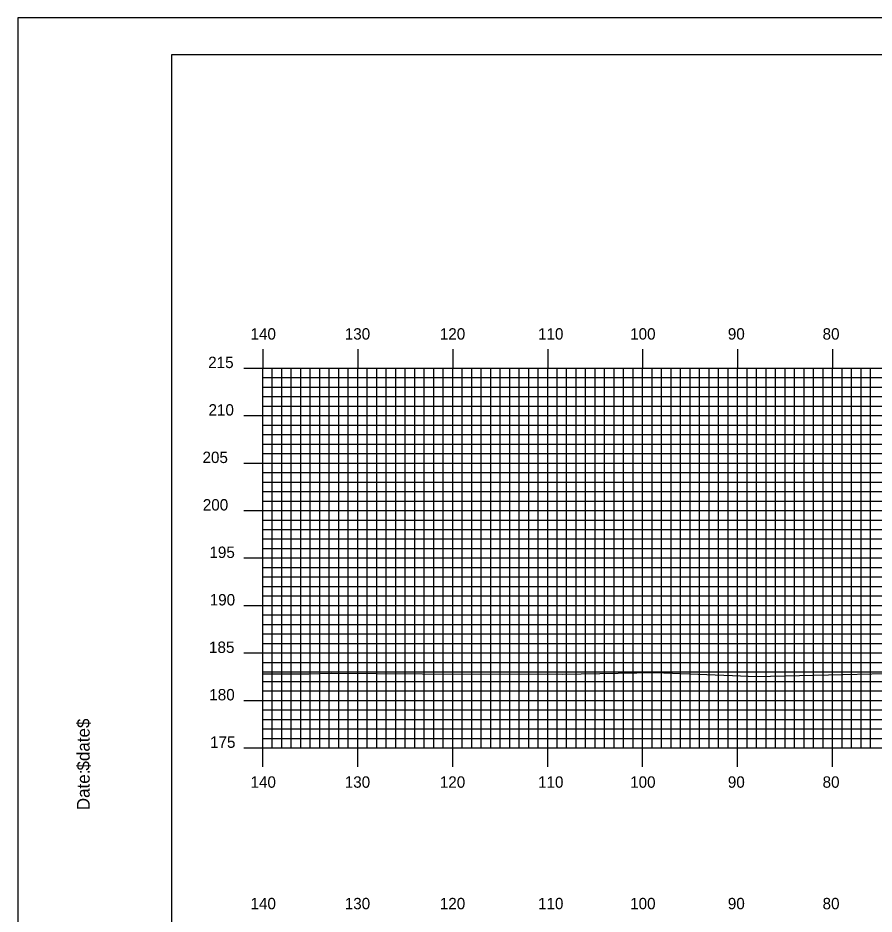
# Model space of a CAD drawing. Extents: x 1809800 to 1810143, y 442591 to 442811.
# Drawn here: x 1809799.6 to 1809889.7, y 442716.2 to 442810.5 of the extents above; entities that cross this region are included whole.
import ezdxf

# ---------------------------------------------------------------- set-up
doc = ezdxf.new("R2010")
doc.units = 0
for name, color, linetype in [('BORDER', 7, 'Continuous'), ('H_V ANNOTATION', 7, 'Continuous'), ('MAJOR', 7, 'Continuous'), ('MINOR', 7, 'Continuous'), ('PLOT BOUNDARY', 7, 'Continuous'), ('S_Roadway_Centerline', 7, 'Continuous')]:
    doc.layers.add(name, color=color, linetype=linetype)

msp = doc.modelspace()

# ---------------------------------------------------------------- linework, layer by layer
at = {"layer": 'BORDER'}
msp.add_lwpolyline([(1809815.75, 442596.665), (1810135.75, 442596.665), (1810135.75, 442806.665), (1809815.75, 442806.665)], close=True, dxfattribs=at)
at = {"layer": 'MAJOR'}
for p, q in [((1809825.35, 442775.669), (1809825.35, 442773.665)), ((1809835.35, 442775.669), (1809835.35, 442773.665)), ((1809845.35, 442775.669), (1809845.35, 442773.665)), ((1809855.35, 442775.669), (1809855.35, 442773.665)), ((1809865.35, 442775.669), (1809865.35, 442773.665)), ((1809875.35, 442775.669), (1809875.35, 442773.665)), ((1809885.35, 442775.669), (1809885.35, 442773.665)), ((1809823.346, 442773.665), (1809825.35, 442773.665)), ((1809825.35, 442773.665), (1810105.35, 442773.665)), ((1809825.35, 442733.665), (1809825.35, 442773.665)), ((1809825.35, 442733.665), (1809825.35, 442773.665)), ((1809825.35, 442773.665), (1810105.35, 442773.665)), ((1809835.35, 442733.665), (1809835.35, 442773.665)), ((1809845.35, 442733.665), (1809845.35, 442773.665)), ((1809855.35, 442733.665), (1809855.35, 442773.665)), ((1809865.35, 442733.665), (1809865.35, 442773.665)), ((1809875.35, 442733.665), (1809875.35, 442773.665)), ((1809885.35, 442733.665), (1809885.35, 442773.665)), ((1809823.346, 442768.665), (1809825.35, 442768.665)), ((1809825.35, 442768.665), (1810105.35, 442768.665)), ((1809823.346, 442763.665), (1809825.35, 442763.665)), ((1809825.35, 442763.665), (1810105.35, 442763.665)), ((1809823.346, 442758.665), (1809825.35, 442758.665)), ((1809825.35, 442758.665), (1810105.35, 442758.665)), ((1809823.346, 442753.665), (1809825.35, 442753.665)), ((1809825.35, 442753.665), (1810105.35, 442753.665)), ((1809823.346, 442748.665), (1809825.35, 442748.665)), ((1809825.35, 442748.665), (1810105.35, 442748.665)), ((1809823.346, 442743.665), (1809825.35, 442743.665)), ((1809825.35, 442743.665), (1810105.35, 442743.665)), ((1809823.346, 442738.665), (1809825.35, 442738.665)), ((1809825.35, 442738.665), (1810105.35, 442738.665)), ((1809823.346, 442733.665), (1809825.35, 442733.665)), ((1809825.35, 442733.665), (1810105.35, 442733.665)), ((1809825.35, 442733.665), (1810105.35, 442733.665)), ((1809825.35, 442731.661), (1809825.35, 442733.665)), ((1809835.35, 442731.661), (1809835.35, 442733.665)), ((1809845.35, 442731.661), (1809845.35, 442733.665)), ((1809855.35, 442731.661), (1809855.35, 442733.665)), ((1809865.35, 442731.661), (1809865.35, 442733.665)), ((1809875.35, 442731.661), (1809875.35, 442733.665)), ((1809885.35, 442731.661), (1809885.35, 442733.665))]:
    msp.add_line(p, q, dxfattribs=at)
at = {"layer": 'MINOR'}
for p, q in [((1809826.35, 442733.665), (1809826.35, 442773.665)), ((1809827.35, 442733.665), (1809827.35, 442773.665)), ((1809828.35, 442733.665), (1809828.35, 442773.665)), ((1809829.35, 442733.665), (1809829.35, 442773.665)), ((1809830.35, 442733.665), (1809830.35, 442773.665)), ((1809831.35, 442733.665), (1809831.35, 442773.665)), ((1809832.35, 442733.665), (1809832.35, 442773.665)), ((1809833.35, 442733.665), (1809833.35, 442773.665)), ((1809834.35, 442733.665), (1809834.35, 442773.665)), ((1809836.35, 442733.665), (1809836.35, 442773.665)), ((1809837.35, 442733.665), (1809837.35, 442773.665)), ((1809838.35, 442733.665), (1809838.35, 442773.665)), ((1809839.35, 442733.665), (1809839.35, 442773.665)), ((1809840.35, 442733.665), (1809840.35, 442773.665)), ((1809841.35, 442733.665), (1809841.35, 442773.665)), ((1809842.35, 442733.665), (1809842.35, 442773.665)), ((1809843.35, 442733.665), (1809843.35, 442773.665)), ((1809844.35, 442733.665), (1809844.35, 442773.665)), ((1809846.35, 442733.665), (1809846.35, 442773.665)), ((1809847.35, 442733.665), (1809847.35, 442773.665)), ((1809848.35, 442733.665), (1809848.35, 442773.665)), ((1809849.35, 442733.665), (1809849.35, 442773.665)), ((1809850.35, 442733.665), (1809850.35, 442773.665)), ((1809851.35, 442733.665), (1809851.35, 442773.665)), ((1809852.35, 442733.665), (1809852.35, 442773.665)), ((1809853.35, 442733.665), (1809853.35, 442773.665)), ((1809854.35, 442733.665), (1809854.35, 442773.665)), ((1809856.35, 442733.665), (1809856.35, 442773.665)), ((1809857.35, 442733.665), (1809857.35, 442773.665)), ((1809858.35, 442733.665), (1809858.35, 442773.665)), ((1809859.35, 442733.665), (1809859.35, 442773.665)), ((1809860.35, 442733.665), (1809860.35, 442773.665)), ((1809861.35, 442733.665), (1809861.35, 442773.665)), ((1809862.35, 442733.665), (1809862.35, 442773.665)), ((1809863.35, 442733.665), (1809863.35, 442773.665)), ((1809864.35, 442733.665), (1809864.35, 442773.665)), ((1809866.35, 442733.665), (1809866.35, 442773.665)), ((1809867.35, 442733.665), (1809867.35, 442773.665)), ((1809868.35, 442733.665), (1809868.35, 442773.665)), ((1809869.35, 442733.665), (1809869.35, 442773.665)), ((1809870.35, 442733.665), (1809870.35, 442773.665)), ((1809871.35, 442733.665), (1809871.35, 442773.665)), ((1809872.35, 442733.665), (1809872.35, 442773.665)), ((1809873.35, 442733.665), (1809873.35, 442773.665)), ((1809874.35, 442733.665), (1809874.35, 442773.665)), ((1809876.35, 442733.665), (1809876.35, 442773.665)), ((1809877.35, 442733.665), (1809877.35, 442773.665)), ((1809878.35, 442733.665), (1809878.35, 442773.665)), ((1809879.35, 442733.665), (1809879.35, 442773.665)), ((1809880.35, 442733.665), (1809880.35, 442773.665)), ((1809881.35, 442733.665), (1809881.35, 442773.665)), ((1809882.35, 442733.665), (1809882.35, 442773.665)), ((1809883.35, 442733.665), (1809883.35, 442773.665)), ((1809884.35, 442733.665), (1809884.35, 442773.665)), ((1809886.35, 442733.665), (1809886.35, 442773.665)), ((1809887.35, 442733.665), (1809887.35, 442773.665)), ((1809888.35, 442733.665), (1809888.35, 442773.665)), ((1809889.35, 442733.665), (1809889.35, 442773.665)), ((1809825.35, 442772.665), (1810105.35, 442772.665)), ((1809825.35, 442772.665), (1809827.354, 442772.665)), ((1809825.35, 442771.665), (1810105.35, 442771.665)), ((1809825.35, 442771.665), (1809827.354, 442771.665)), ((1809825.35, 442770.665), (1810105.35, 442770.665)), ((1809825.35, 442770.665), (1809827.354, 442770.665)), ((1809825.35, 442769.665), (1810105.35, 442769.665)), ((1809825.35, 442769.665), (1809827.354, 442769.665)), ((1809825.35, 442767.665), (1810105.35, 442767.665)), ((1809825.35, 442767.665), (1809827.354, 442767.665)), ((1809825.35, 442766.665), (1810105.35, 442766.665)), ((1809825.35, 442766.665), (1809827.354, 442766.665)), ((1809825.35, 442765.665), (1810105.35, 442765.665)), ((1809825.35, 442765.665), (1809827.354, 442765.665)), ((1809825.35, 442764.665), (1810105.35, 442764.665)), ((1809825.35, 442764.665), (1809827.354, 442764.665)), ((1809825.35, 442762.665), (1810105.35, 442762.665)), ((1809825.35, 442762.665), (1809827.354, 442762.665)), ((1809825.35, 442761.665), (1810105.35, 442761.665)), ((1809825.35, 442761.665), (1809827.354, 442761.665)), ((1809825.35, 442760.665), (1810105.35, 442760.665)), ((1809825.35, 442760.665), (1809827.354, 442760.665)), ((1809825.35, 442759.665), (1810105.35, 442759.665)), ((1809825.35, 442759.665), (1809827.354, 442759.665)), ((1809825.35, 442757.665), (1810105.35, 442757.665)), ((1809825.35, 442757.665), (1809827.354, 442757.665)), ((1809825.35, 442756.665), (1810105.35, 442756.665)), ((1809825.35, 442756.665), (1809827.354, 442756.665)), ((1809825.35, 442755.665), (1810105.35, 442755.665)), ((1809825.35, 442755.665), (1809827.354, 442755.665)), ((1809825.35, 442754.665), (1810105.35, 442754.665)), ((1809825.35, 442754.665), (1809827.354, 442754.665)), ((1809825.35, 442752.665), (1810105.35, 442752.665)), ((1809825.35, 442752.665), (1809827.354, 442752.665)), ((1809825.35, 442751.665), (1810105.35, 442751.665)), ((1809825.35, 442751.665), (1809827.354, 442751.665)), ((1809825.35, 442750.665), (1810105.35, 442750.665)), ((1809825.35, 442750.665), (1809827.354, 442750.665)), ((1809825.35, 442749.665), (1810105.35, 442749.665)), ((1809825.35, 442749.665), (1809827.354, 442749.665)), ((1809825.35, 442747.665), (1810105.35, 442747.665)), ((1809825.35, 442747.665), (1809827.354, 442747.665)), ((1809825.35, 442746.665), (1810105.35, 442746.665)), ((1809825.35, 442746.665), (1809827.354, 442746.665)), ((1809825.35, 442745.665), (1810105.35, 442745.665)), ((1809825.35, 442745.665), (1809827.354, 442745.665)), ((1809825.35, 442744.665), (1810105.35, 442744.665)), ((1809825.35, 442744.665), (1809827.354, 442744.665)), ((1809825.35, 442742.665), (1810105.35, 442742.665)), ((1809825.35, 442742.665), (1809827.354, 442742.665)), ((1809825.35, 442741.665), (1810105.35, 442741.665)), ((1809825.35, 442741.665), (1809827.354, 442741.665)), ((1809825.35, 442740.665), (1810105.35, 442740.665)), ((1809825.35, 442740.665), (1809827.354, 442740.665)), ((1809825.35, 442739.665), (1810105.35, 442739.665)), ((1809825.35, 442739.665), (1809827.354, 442739.665)), ((1809825.35, 442737.665), (1810105.35, 442737.665)), ((1809825.35, 442737.665), (1809827.354, 442737.665)), ((1809825.35, 442736.665), (1810105.35, 442736.665)), ((1809825.35, 442736.665), (1809827.354, 442736.665)), ((1809825.35, 442735.665), (1810105.35, 442735.665)), ((1809825.35, 442735.665), (1809827.354, 442735.665)), ((1809825.35, 442734.665), (1810105.35, 442734.665)), ((1809825.35, 442734.665), (1809827.354, 442734.665))]:
    msp.add_line(p, q, dxfattribs=at)
at = {"layer": 'PLOT BOUNDARY'}
msp.add_lwpolyline([(1809799.564, 442590.547), (1810139.564, 442590.547), (1810139.564, 442810.547), (1809799.564, 442810.547)], close=True, dxfattribs=at)
at = {"layer": 'S_Roadway_Centerline'}
msp.add_lwpolyline([(1809825.35, 442741.451), (1809830.203, 442741.479), (1809832.611, 442741.529), (1809842.155, 442741.48), (1809856.934, 442741.444), (1809866.66, 442741.604), (1809874.804, 442741.278), (1809877.292, 442741.187), (1809898.611, 442741.656)], dxfattribs=at)

# ---------------------------------------------------------------- texts
at = {"layer": 'BORDER'}
for s, p in [('$date$', (1809807.12, 442731.275)), ('Date:', (1809807.12, 442727.099))]:
    msp.add_text(s, height=1.3392, rotation=90, dxfattribs=at).set_placement(p)
at = {"layer": 'H_V ANNOTATION'}
for s, p in [('140', (1809824.055, 442776.665)), ('130', (1809833.98, 442776.665)), ('120', (1809843.991, 442776.665)), ('110', (1809854.334, 442776.665)), ('100', (1809864.034, 442776.665)), ('90', (1809874.323, 442776.665)), ('80', (1809884.301, 442776.665)), ('215', (1809819.599, 442773.665)), ('210', (1809819.631, 442768.665)), ('205', (1809819, 442763.665)), ('200', (1809819.032, 442758.665)), ('195', (1809819.728, 442753.665)), ('190', (1809819.76, 442748.665)), ('185', (1809819.685, 442743.665)), ('180', (1809819.717, 442738.665)), ('175', (1809819.792, 442733.665)), ('140', (1809824.055, 442729.465)), ('130', (1809833.98, 442729.465)), ('120', (1809843.991, 442729.465)), ('110', (1809854.334, 442729.465)), ('100', (1809864.034, 442729.465)), ('90', (1809874.323, 442729.465)), ('80', (1809884.301, 442729.465)), ('140', (1809824.055, 442716.665)), ('130', (1809833.98, 442716.665)), ('120', (1809843.991, 442716.665)), ('110', (1809854.334, 442716.665)), ('100', (1809864.034, 442716.665)), ('90', (1809874.323, 442716.665)), ('80', (1809884.301, 442716.665))]:
    msp.add_text(s, height=1.2, dxfattribs=at).set_placement(p)
at = {"layer": 'MAJOR'}
msp.add_text('-', height=0.012, dxfattribs=at).set_placement((1809825.341, 442733.665))

doc.saveas('drawing.dxf')
